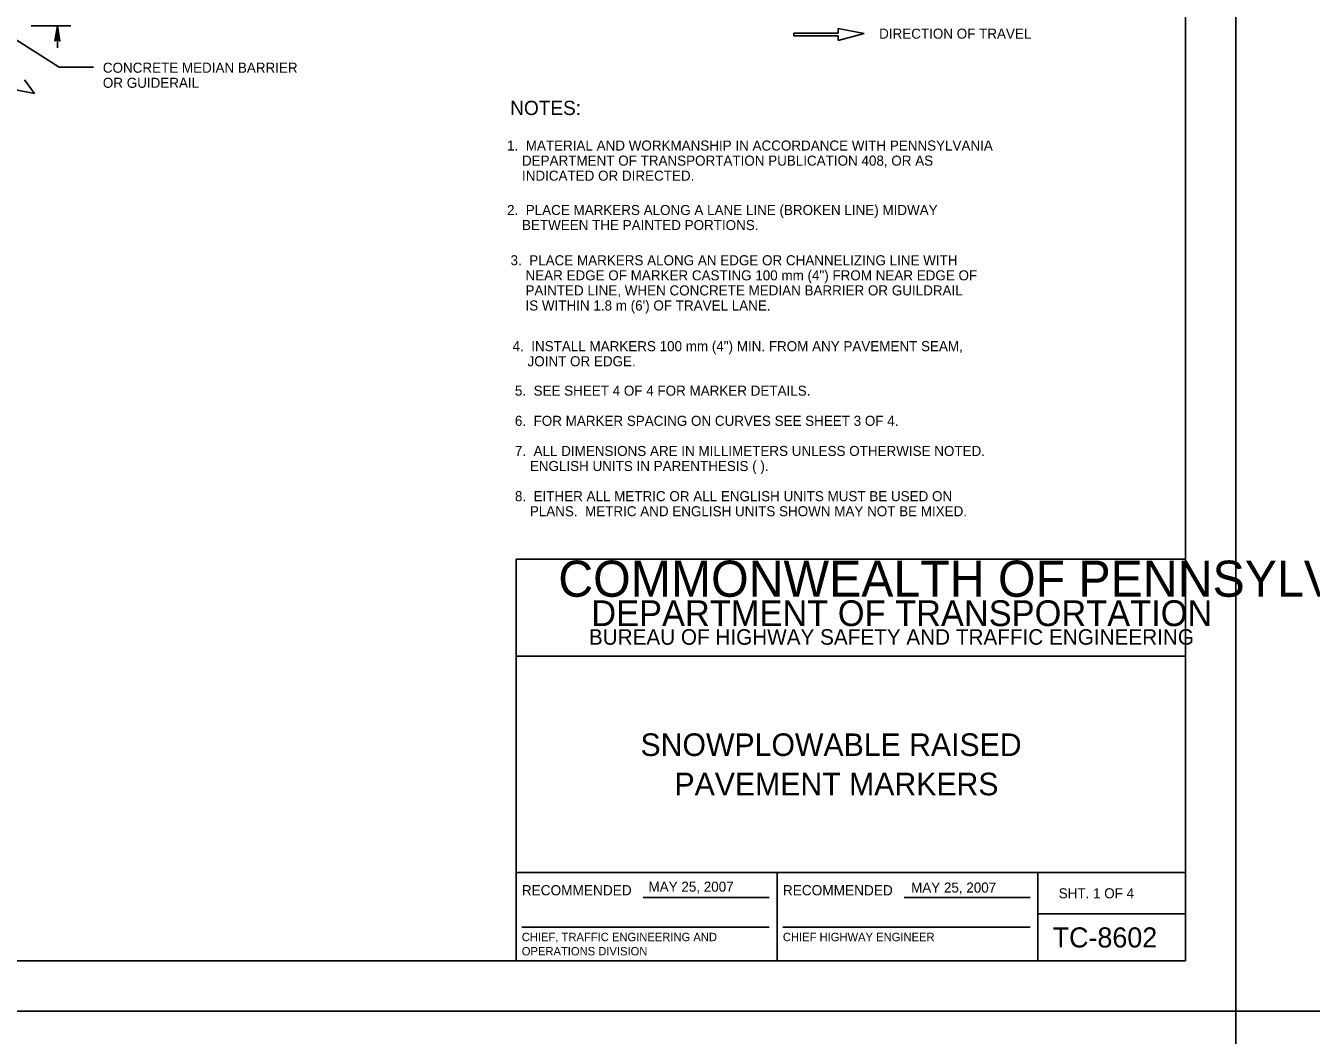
# Model space of a CAD drawing. Extents: x 639362 to 641108, y 298458 to 299646.
# Drawn here: x 639841.8 to 640225.9, y 299044.4 to 299345.9 of the extents above; entities that cross this region are included whole.
import ezdxf

# ---------------------------------------------------------------- set-up
doc = ezdxf.new("R2010")
doc.units = 0
for name, color, linetype in [('1', 7, 'Continuous'), ('2', 7, 'Continuous'), ('PLT-BNDY', 7, 'Continuous')]:
    doc.layers.add(name, color=color, linetype=linetype)

msp = doc.modelspace()

# ---------------------------------------------------------------- linework, layer by layer
at = {"layer": '1'}
for p, q in [((640188.31, 299066.63), (640188.31, 299630.63)), ((639988.31, 299066.63), (639988.31, 299186.63)), ((639988.31, 299186.63), (640188.31, 299186.63)), ((640188.31, 299157.63), (639988.31, 299157.63)), ((639988.31, 299093), (640188.31, 299093)), ((640066.31, 299093), (640066.31, 299066.63)), ((640144.19, 299066.63), (640144.19, 299093)), ((640026.24, 299085.57), (640063.87, 299085.57)), ((640104.24, 299085.57), (640141.87, 299085.57)), ((640144.19, 299080.63), (640188.31, 299080.63)), ((639989.99, 299076.68), (640063.87, 299076.68)), ((640067.99, 299076.68), (640141.87, 299076.68)), ((640188.31, 299066.63), (639402.31, 299066.63)), ((639402.31, 299066.63), (639988.31, 299066.63))]:
    msp.add_line(p, q, dxfattribs=at)
at = {"layer": '2'}
for p, q in [((639843.43, 299345.83), (639855.25, 299345.83)), ((639851.25, 299345.83), (639851.25, 299339.28)), ((640092.28, 299343.58), (640084.47, 299345.06)), ((640084.47, 299345.06), (640084.47, 299343.61)), ((639836.76, 299343.11), (639851.76, 299333.52)), ((640084.47, 299343.61), (640071.23, 299343.61)), ((640071.23, 299343.61), (640071.23, 299342.91)), ((640071.23, 299342.91), (640084.55, 299342.91)), ((640084.55, 299341.47), (640092.28, 299343.58)), ((640084.55, 299342.91), (640084.55, 299341.47)), ((639851.76, 299333.52), (639862.07, 299333.52)), ((639844.38, 299325.62), (639841.43, 299329.76)), ((639838.86, 299326.76), (639844.38, 299325.62))]:
    msp.add_line(p, q, dxfattribs=at)
msp.add_lwpolyline([(639850.71, 299341.51), (639851.02, 299341.67), (639851.25, 299345.83), (639850.71, 299341.51), (639850.52, 299341.28), (639851.25, 299345.83), (639851.46, 299341.67), (639851.77, 299341.52), (639851.25, 299345.83), (639851.97, 299341.28), (639851.77, 299341.52)], dxfattribs=at)
at = {"layer": 'PLT-BNDY'}
for points in [[(639362.31, 299645.63), (640203.31, 299645.63), (640203.31, 299051.63), (639362.31, 299051.63)], [(640203.31, 299645.63), (641044.31, 299645.63), (641044.31, 299051.63), (640203.31, 299051.63)], [(639362.31, 299051.63), (640203.31, 299051.63), (640203.31, 298457.63), (639362.31, 298457.63)], [(640203.31, 299051.63), (641044.31, 299051.63), (641044.31, 298457.63), (640203.31, 298457.63)]]:
    msp.add_lwpolyline(points, close=True, dxfattribs=at)

# ---------------------------------------------------------------- texts
at = {"layer": '1'}
for s, height, p in [('COMMONWEALTH OF PENNSYLVANIA', 10.7828, (640000.9, 299175.36)), ('DEPARTMENT OF TRANSPORTATION', 7.6837, (640010.76, 299166.61)), ('BUREAU OF HIGHWAY SAFETY AND TRAFFIC ENGINEERING', 4.6253, (640010.04, 299161.04)), ('SNOWPLOWABLE RAISED', 6.75, (640025.46, 299127.81)), ('PAVEMENT MARKERS', 6.75, (640035.61, 299116.06)), ('RECOMMENDED', 3.048, (639989.99, 299086.2)), ('RECOMMENDED', 3.048, (640067.99, 299086.2)), ('SHT. 1 OF 4', 3, (640150.4, 299085.31)), ('TC-8602', 6, (640148.6, 299070.63)), ('CHIEF, TRAFFIC ENGINEERING AND', 2.5, (639989.99, 299072.51)), ('CHIEF HIGHWAY ENGINEER', 2.5, (640067.99, 299072.51)), ('OPERATIONS DIVISION', 2.5, (639989.99, 299068.26))]:
    msp.add_text(s, height=height, dxfattribs=at).set_placement(p)
at = {"layer": '2'}
for s, height, p in [('DIRECTION OF TRAVEL', 3, (640096.75, 299342.01)), ('CONCRETE MEDIAN BARRIER', 3, (639864.84, 299331.84)), ('OR GUIDERAIL', 3, (639864.84, 299327.34)), ('NOTES:', 4.25, (639986.54, 299319.21)), ('1.  MATERIAL AND WORKMANSHIP IN ACCORDANCE WITH PENNSYLVANIA', 3, (639985.6, 299308.6)), ('    DEPARTMENT OF TRANSPORTATION PUBLICATION 408, OR AS', 3, (639985.6, 299304.1)), ('    INDICATED OR DIRECTED.', 3, (639985.6, 299299.6)), ('2.  PLACE MARKERS ALONG A LANE LINE (BROKEN LINE) MIDWAY', 3, (639985.6, 299289.35)), ('    BETWEEN THE PAINTED PORTIONS.', 3, (639985.6, 299284.85)), ('3.  PLACE MARKERS ALONG AN EDGE OR CHANNELIZING LINE WITH ', 3, (639986.64, 299274.34)), ('    NEAR EDGE OF MARKER CASTING 100 mm (4") FROM NEAR EDGE OF ', 3, (639986.64, 299269.84)), ('    PAINTED LINE, WHEN CONCRETE MEDIAN BARRIER OR GUILDRAIL', 3, (639986.64, 299265.34)), ("    IS WITHIN 1.8 m (6') OF TRAVEL LANE.", 3, (639986.64, 299260.84)), ('4.  INSTALL MARKERS 100 mm (4") MIN. FROM ANY PAVEMENT SEAM,', 3, (639987.25, 299248.69)), ('    JOINT OR EDGE.', 3, (639987.25, 299244.19)), ('5.  SEE SHEET 4 OF 4 FOR MARKER DETAILS.', 3, (639987.94, 299235.4)), ('6.  FOR MARKER SPACING ON CURVES SEE SHEET 3 OF 4.', 3, (639987.94, 299226.4)), ('7.  ALL DIMENSIONS ARE IN MILLIMETERS UNLESS OTHERWISE NOTED.', 3, (639987.94, 299217.4)), ('    ENGLISH UNITS IN PARENTHESIS ( ).', 3, (639987.94, 299212.9)), ('8.  EITHER ALL METRIC OR ALL ENGLISH UNITS MUST BE USED ON', 3, (639987.94, 299203.9)), ('    PLANS.  METRIC AND ENGLISH UNITS SHOWN MAY NOT BE MIXED.', 3, (639987.94, 299199.4)), ('MAY 25, 2007', 3, (640027.86, 299087.28)), ('MAY 25, 2007', 3, (640106.3, 299087.02))]:
    msp.add_text(s, height=height, dxfattribs=at).set_placement(p)

doc.saveas('drawing.dxf')
